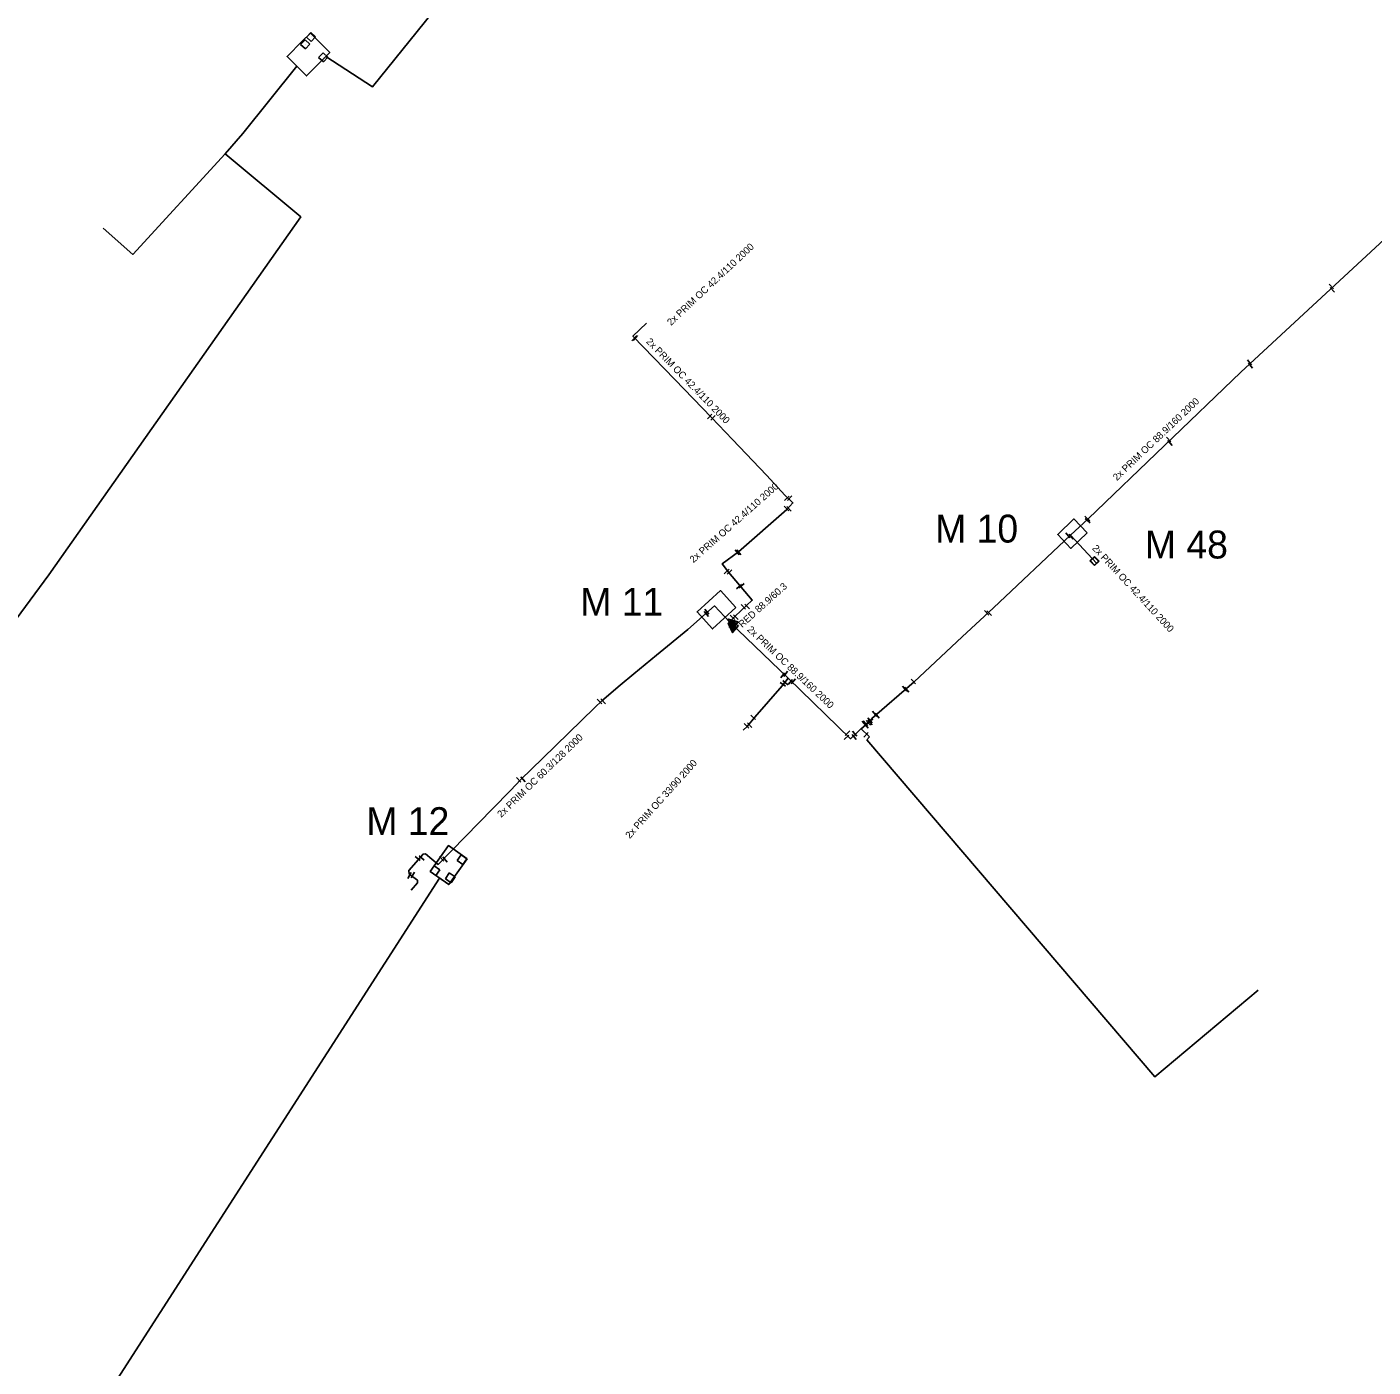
# Model space of a CAD drawing. Extents: x -642943 to -623314, y -1138561 to -1113539.
# Drawn here: x -642361.3 to -642216.7, y -1115211.3 to -1115067.2 of the extents above; entities that cross this region are included whole.
import ezdxf

# ---------------------------------------------------------------- set-up
doc = ezdxf.new("R2010")
doc.units = 0
for name, color, linetype in [('horkovod armatury', 7, 'Continuous'), ('horkovod dimenze', 7, 'Continuous'), ('horkovod předisol', 7, 'Continuous'), ('horkovod sváry', 7, 'Continuous'), ('horkovod trasa', 7, 'Continuous'), ('horkovod zrušený', 7, 'Continuous'), ('horkovod číslo šachty', 7, 'Continuous'), ('horkovod šachty', 7, 'Continuous')]:
    doc.layers.add(name, color=color, linetype=linetype)

# ---------------------------------------------------------------- blocks, each defined once
blk = doc.blocks.new('SPH')
at = {"layer": 'horkovod sváry'}
blk.add_line((0, -0.035), (0, 0.035), dxfattribs=at)
blk = doc.blocks.new('POINT_DISPLAY')
blk.add_line((0, 0), (0, 0))
blk = doc.blocks.new('SREDU')
at = {"layer": 'horkovod armatury'}
for points in [[(-0.05, -0.05), (0.051, 0), (-0.05, 0.05), (-0.05, -0.05)], [(-0.034, -0.025), (0.018, 0), (-0.034, 0.025), (-0.034, -0.025)], [(-0.025, -0.012), (0.001, 0), (-0.025, 0.012), (-0.025, -0.012)]]:
    blk.add_lwpolyline(points, dxfattribs=at)

msp = doc.modelspace()

# ---------------------------------------------------------------- linework, layer by layer
at = {"layer": 'horkovod předisol'}
for p, q in [((-642249.21, -1115121.86), (-642246.37, -1115124.91)), ((-642279.54, -1115137.23), (-642285.84, -1115131.16))]:
    msp.add_line(p, q, dxfattribs=at)
for points in [[(-642194.19, -1115070.71), (-642203.14, -1115078.74), (-642210.42, -1115085.39), (-642214.98, -1115089.6), (-642230.9, -1115104.35), (-642247.3, -1115120.1), (-642249.21, -1115121.86)], [(-642284.87, -1115123.65), (-642279.69, -1115119.09), (-642279.03, -1115118.38), (-642279.85, -1115117.58), (-642281.88, -1115115.42), (-642285.53, -1115111.57), (-642287.77, -1115109.22), (-642291.74, -1115105.12), (-642296.23, -1115100.48), (-642294.77, -1115099.06)], [(-642249.21, -1115121.86), (-642257.49, -1115129.67), (-642260.83, -1115132.77), (-642266.02, -1115137.62), (-642270.55, -1115141.56)], [(-642285.84, -1115131.16), (-642285.23, -1115130.56), (-642283.4, -1115128.84), (-642285.95, -1115125.84), (-642286.65, -1115124.94), (-642284.87, -1115123.65)], [(-642285.84, -1115131.16), (-642287.45, -1115129.45), (-642290.33, -1115131.99), (-642293.71, -1115134.74), (-642296.12, -1115136.74), (-642297.6, -1115137.99), (-642299.56, -1115139.67), (-642300.31, -1115140.39), (-642305.95, -1115145.86), (-642308.26, -1115148.1), (-642309.4, -1115149.28), (-642311.31, -1115151.27), (-642317.17, -1115157.24), (-642318.51, -1115156.1), (-642318.77, -1115156.13), (-642320.31, -1115157.9), (-642320.26, -1115158.27), (-642319.39, -1115158.94), (-642319.37, -1115159.2), (-642320.04, -1115160.01)], [(-642279.54, -1115137.23), (-642280.19, -1115138.04), (-642283.11, -1115141.41), (-642283.95, -1115142.4), (-642284.39, -1115142.8)], [(-642270.55, -1115141.56), (-642272.86, -1115143.73), (-642279.54, -1115137.23)], [(-642270.55, -1115141.56), (-642270.48, -1115141.63), (-642271.69, -1115142.68), (-642270.87, -1115143.46)]]:
    msp.add_lwpolyline(points, dxfattribs=at)
at = {"layer": 'horkovod trasa'}
for p, q in [((-642249.21, -1115121.86), (-642246.37, -1115124.91)), ((-642279.54, -1115137.23), (-642285.84, -1115131.16)), ((-642271.08, -1115143.84), (-642270.79, -1115143.54)), ((-642270.87, -1115143.46), (-642270.79, -1115143.54))]:
    msp.add_line(p, q, dxfattribs=at)
for points in [[(-642329.22, -1115070.42), (-642324.22, -1115073.68), (-642296.32, -1115039.07), (-642267.43, -1115007.95), (-642277.18, -1114996), (-642304.7, -1114983.75), (-642293.54, -1114943.83), (-642293.69, -1114923.7)], [(-642332.35, -1115071.45), (-642338.16, -1115078.7), (-642340.05, -1115080.88), (-642331.92, -1115087.66), (-642359.01, -1115126.11), (-642369.97, -1115140.94), (-642374.96, -1115138.17)], [(-642194.19, -1115070.71), (-642203.14, -1115078.74), (-642210.42, -1115085.39), (-642214.98, -1115089.6), (-642230.9, -1115104.35), (-642247.3, -1115120.1), (-642249.21, -1115121.86)], [(-642340.05, -1115080.88), (-642349.96, -1115091.69), (-642353.15, -1115088.86)], [(-642284.87, -1115123.65), (-642279.69, -1115119.09), (-642279.03, -1115118.38), (-642279.85, -1115117.58), (-642281.88, -1115115.42), (-642285.53, -1115111.57), (-642287.77, -1115109.22), (-642291.74, -1115105.12), (-642296.23, -1115100.48), (-642294.77, -1115099.06)], [(-642249.21, -1115121.86), (-642257.49, -1115129.67), (-642260.83, -1115132.77), (-642266.02, -1115137.62), (-642270.55, -1115141.56)], [(-642285.84, -1115131.16), (-642285.23, -1115130.56), (-642283.4, -1115128.84), (-642285.95, -1115125.84), (-642286.65, -1115124.94), (-642284.87, -1115123.65)], [(-642285.84, -1115131.16), (-642287.45, -1115129.45), (-642290.33, -1115131.99), (-642293.71, -1115134.74), (-642296.12, -1115136.74), (-642297.6, -1115137.99), (-642299.56, -1115139.67), (-642300.31, -1115140.39), (-642305.95, -1115145.86), (-642308.26, -1115148.1), (-642309.4, -1115149.28), (-642311.31, -1115151.27), (-642317.17, -1115157.24), (-642318.51, -1115156.1), (-642318.77, -1115156.13), (-642320.31, -1115157.9), (-642320.26, -1115158.27), (-642319.39, -1115158.94), (-642319.37, -1115159.2), (-642320.04, -1115160.01)], [(-642279.54, -1115137.23), (-642280.19, -1115138.04), (-642283.11, -1115141.41), (-642283.95, -1115142.4), (-642284.39, -1115142.8)], [(-642270.55, -1115141.56), (-642272.86, -1115143.73), (-642279.54, -1115137.23)], [(-642270.55, -1115141.56), (-642270.48, -1115141.63), (-642271.69, -1115142.68), (-642270.87, -1115143.46)], [(-642271.08, -1115143.84), (-642240.15, -1115180.05), (-642229.02, -1115170.76)]]:
    msp.add_lwpolyline(points, dxfattribs=at)
at = {"layer": 'horkovod zrušený'}
msp.add_line((-642358.66, -1115223.47), (-642317.01, -1115158.7), dxfattribs=at)
for points in [[(-642247.42, -1115121.62), (-642248.84, -1115120.11), (-642250.57, -1115121.78), (-642249.16, -1115123.27), (-642247.42, -1115121.62)], [(-642285.18, -1115129.62), (-642286.83, -1115127.81), (-642289.34, -1115130.11), (-642287.68, -1115131.92), (-642285.18, -1115129.62)], [(-642314.05, -1115156.62), (-642316.06, -1115155.21), (-642318.01, -1115157.99), (-642316.01, -1115159.4), (-642314.05, -1115156.62)]]:
    msp.add_lwpolyline(points, dxfattribs=at)
at = {"layer": 'horkovod šachty'}
for p, q in [((-642331.46, -1115068.61), (-642331.94, -1115069.11)), ((-642330.95, -1115069.09), (-642331.46, -1115068.61)), ((-642330.84, -1115067.82), (-642331.32, -1115068.33)), ((-642331.32, -1115068.33), (-642330.81, -1115068.8)), ((-642330.33, -1115068.29), (-642330.84, -1115067.82)), ((-642330.81, -1115068.8), (-642330.33, -1115068.29)), ((-642331.94, -1115069.11), (-642331.43, -1115069.59)), ((-642331.43, -1115069.59), (-642330.95, -1115069.09)), ((-642329.53, -1115070.02), (-642330, -1115070.53)), ((-642329.01, -1115070.49), (-642329.53, -1115070.02)), ((-642330, -1115070.53), (-642329.48, -1115071)), ((-642329.48, -1115071), (-642329.01, -1115070.49)), ((-642247.12, -1115124.61), (-642246.61, -1115124.14)), ((-642246.64, -1115125.13), (-642247.12, -1115124.61)), ((-642247.05, -1115124.62), (-642246.61, -1115124.21)), ((-642246.64, -1115125.06), (-642247.05, -1115124.62)), ((-642246.64, -1115125.13), (-642246.13, -1115124.65)), ((-642246.64, -1115125.06), (-642246.2, -1115124.65)), ((-642246.61, -1115124.14), (-642246.13, -1115124.65)), ((-642246.61, -1115124.21), (-642246.2, -1115124.65)), ((-642314.7, -1115156.21), (-642315.13, -1115156.82)), ((-642315.13, -1115156.82), (-642314.52, -1115157.25)), ((-642314.09, -1115156.64), (-642314.7, -1115156.21)), ((-642314.52, -1115157.25), (-642314.09, -1115156.64)), ((-642317.58, -1115157.38), (-642318.01, -1115157.99)), ((-642318.01, -1115157.99), (-642317.4, -1115158.42)), ((-642316.96, -1115157.81), (-642317.58, -1115157.38)), ((-642317.4, -1115158.42), (-642316.96, -1115157.81)), ((-642315.96, -1115158.16), (-642316.38, -1115158.78)), ((-642315.34, -1115158.57), (-642315.96, -1115158.16)), ((-642315.75, -1115159.2), (-642315.34, -1115158.57)), ((-642316.38, -1115158.78), (-642315.75, -1115159.2))]:
    msp.add_line(p, q, dxfattribs=at)
msp.add_lwpolyline([(-642331.77, -1115068.78), (-642333.39, -1115070.41), (-642331.31, -1115072.49), (-642328.8, -1115069.98), (-642330.88, -1115067.9), (-642331.77, -1115068.78)], dxfattribs=at)

# ---------------------------------------------------------------- block references
at = {"layer": 'horkovod armatury'}
for p, xscale, yscale, rotation in [((-642285.61, -1115131.21), 10.000004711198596, 10.000004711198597, 138.02346569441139), ((-642285.58, -1115131.62), 9.9999987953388, 9.999998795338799, 140.7128512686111)]:
    msp.add_blockref('SREDU', p, dxfattribs=dict(at, xscale=xscale, yscale=yscale, rotation=rotation))
at = {"layer": 'horkovod sváry'}
for p, xscale, yscale, rotation in [((-642221.17, -1115095.14), 9.999996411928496, 9.999996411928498, 43.44789718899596), ((-642221.07, -1115095.49), 9.999984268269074, 9.999984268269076, 42.9943262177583), ((-642296.1, -1115100.71), 10.000000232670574, 10.000000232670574, -42.781943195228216), ((-642295.96, -1115100.67), 10.000000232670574, 10.000000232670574, -42.781943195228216), ((-642229.98, -1115103.3), 9.999977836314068, 9.999977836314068, 38.39150709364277), ((-642229.86, -1115103.63), 9.999989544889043, 9.999989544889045, 41.04235929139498), ((-642287.97, -1115109.11), 10.000000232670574, 10.000000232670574, -42.781943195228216), ((-642287.62, -1115109.25), 9.99999797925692, 9.99999797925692, -43.108534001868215), ((-642238.66, -1115111.57), 9.999989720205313, 9.999989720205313, 41.5915519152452), ((-642238.52, -1115111.94), 9.999986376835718, 9.999986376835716, 40.61220467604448), ((-642279.69, -1115117.9), 9.99998715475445, 9.99998715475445, -46.18675416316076), ((-642279.39, -1115117.88), 9.999986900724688, 9.99998690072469, -43.898348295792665), ((-642279.72, -1115118.99), 10.000012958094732, 10.000012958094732, 43.5228236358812), ((-642279.45, -1115119.01), 10.00000408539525, 10.00000408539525, 44.620603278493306), ((-642247.39, -1115120.06), 10.000013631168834, 10.000013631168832, 47.429337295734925), ((-642247.37, -1115120.3), 10.000003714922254, 10.000003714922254, 49.01039855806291), ((-642249.5, -1115121.87), 10.0000269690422, 10.0000269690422, 37.93893657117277), ((-642249.12, -1115122.01), 10.000018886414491, 10.000018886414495, 37.65197844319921), ((-642285.03, -1115123.69), 10.000014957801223, 10.000014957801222, 38.072739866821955), ((-642284.84, -1115123.71), 10.000008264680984, 10.000008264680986, 40.0301448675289), ((-642286.15, -1115125.76), 9.999996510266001, 9.999996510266, -47.531690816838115), ((-642285.85, -1115125.81), 9.9999887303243, 9.9999887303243, -46.34111516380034), ((-642284.82, -1115127.39), 9.999992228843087, 9.999992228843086, -48.39597371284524), ((-642284.54, -1115127.28), 10.000002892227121, 10.000002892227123, -49.50340681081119), ((-642284.37, -1115129.55), 10.000026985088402, 10.000026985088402, 41.76032102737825), ((-642283.94, -1115129.53), 9.99999804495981, 9.999998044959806, 44.50193274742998), ((-642288.33, -1115130.33), 10.000016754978, 10.000016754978, 41.88389081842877), ((-642288.28, -1115130.07), 10.00002500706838, 10.00002500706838, 40.64892818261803), ((-642285.53, -1115130.68), 10.000007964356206, 10.000007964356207, 48.97824667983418), ((-642285.16, -1115130.66), 9.999995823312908, 9.999995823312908, 46.67912126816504), ((-642258.21, -1115130.21), 10.000004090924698, 10.000004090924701, 44.00647008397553), ((-642257.93, -1115130.23), 9.999980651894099, 9.999980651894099, 46.14788295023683), ((-642285.64, -1115131.51), 9.999993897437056, 9.999993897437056, -40.45419727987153), ((-642285.35, -1115131.52), 10.000017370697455, 10.000017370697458, -39.84567585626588), ((-642280.13, -1115136.92), 10.000000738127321, 10.00000073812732, -36.25378036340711), ((-642279.81, -1115136.76), 9.99999068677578, 9.999990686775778, -36.87000436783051), ((-642280.13, -1115137.88), 9.999986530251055, 9.999986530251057, 54.226417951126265), ((-642279.85, -1115137.71), 9.99998986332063, 9.99998986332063, 49.690788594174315), ((-642279.31, -1115137.63), 10.000009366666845, 10.000009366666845, -42.14931473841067), ((-642278.98, -1115137.56), 9.999984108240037, 9.999984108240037, -42.30437881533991), ((-642267.02, -1115138.35), 9.999996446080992, 9.99999644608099, 43.024909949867), ((-642266.8, -1115138.46), 9.999978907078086, 9.999978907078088, 43.175917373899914), ((-642266.09, -1115137.58), 10.00000528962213, 10.00000528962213, 44.31515034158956), ((-642299.82, -1115139.73), 10.000008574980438, 10.00000857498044, 43.12967723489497), ((-642299.42, -1115139.71), 9.999985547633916, 9.999985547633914, 43.66775382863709), ((-642283.31, -1115141.43), 10.000020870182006, 10.000020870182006, 46.577954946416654), ((-642270.25, -1115141.06), 9.999989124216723, 9.999989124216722, 38.290086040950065), ((-642269.98, -1115141.25), 9.999997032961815, 9.999997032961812, 37.75695230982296), ((-642284.03, -1115142.34), 9.999997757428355, 9.999997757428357, 46.5936233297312), ((-642283.68, -1115142.28), 10.000000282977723, 10.000000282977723, 45.18262262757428), ((-642271.36, -1115142.11), 10.000020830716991, 10.000020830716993, 39.06265595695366), ((-642271.25, -1115142.08), 10.000005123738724, 10.000005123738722, 39.66076319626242), ((-642271.16, -1115142.32), 10.000021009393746, 10.000021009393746, 38.93631690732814), ((-642270.94, -1115142.02), 10.000008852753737, 10.000008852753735, 41.440729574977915), ((-642270.76, -1115141.76), 10.000006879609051, 10.000006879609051, 41.34791341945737), ((-642270.74, -1115141.97), 9.999979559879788, 9.999979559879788, 42.13759477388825), ((-642273.28, -1115143.58), 10.000007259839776, 10.000007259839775, -48.441705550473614), ((-642273.16, -1115143.13), 10.00003058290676, 10.000030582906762, -46.034095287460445), ((-642272.46, -1115143.54), 10.000001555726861, 10.000001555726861, 38.380507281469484), ((-642272.39, -1115143.17), 10.000015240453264, 10.000015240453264, 40.256976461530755), ((-642271.17, -1115143.31), 10.00000810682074, 10.00000810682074, -42.75173651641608), ((-642308.5, -1115148.15), 9.999999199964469, 9.999999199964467, 42.169523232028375), ((-642308.05, -1115148.09), 9.999985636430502, 9.999985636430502, 42.967331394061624), ((-642319.35, -1115156.6), 9.999979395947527, 9.999979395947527, 49.47276051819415), ((-642318.93, -1115156.54), 10.000006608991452, 10.000006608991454, 47.31906729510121), ((-642316.77, -1115156.63), 9.999980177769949, 9.999980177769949, 43.349941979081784), ((-642316.42, -1115156.71), 9.999993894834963, 9.99999389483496, 39.45456601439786), ((-642320.23, -1115158.43), 10.000022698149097, 10.000022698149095, -29.054578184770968), ((-642319.88, -1115158.38), 10.000003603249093, 10.000003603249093, -32.03708647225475)]:
    msp.add_blockref('SPH', p, dxfattribs=dict(at, xscale=xscale, yscale=yscale, rotation=rotation))
at = {"layer": 'horkovod šachty'}
for p in [(-642330.82, -1115068.31), (-642331.44, -1115069.1), (-642329.5, -1115070.51), (-642246.62, -1115124.64), (-642314.6, -1115156.73), (-642317.48, -1115157.9), (-642315.85, -1115158.67)]:
    msp.add_blockref('POINT_DISPLAY', p, dxfattribs=at)

# ---------------------------------------------------------------- texts
at = {"layer": 'horkovod dimenze'}
for s, rotation, p in [('2x PRIM OC 42.4/110 2000', 43.1913, (-642292.13, -1115099.38)), ('2x PRIM OC 42.4/110 2000', 314.1873, (-642294.86, -1115101.11)), ('2x PRIM OC 88.9/160 2000', 43.6144, (-642244.22, -1115116.05)), ('2x PRIM OC 42.4/110 2000', 41.5128, (-642289.73, -1115124.88)), ('2x PRIM OC 42.4/110 2000', 312.786, (-642246.93, -1115123.31)), ('RED 88.9/60.3', 41.8077, (-642284.49, -1115131.84)), ('2x PRIM OC 88.9/160 2000', 316.5941, (-642284.01, -1115132.08)), ('2x PRIM OC 60.3/128 2000', 44.1289, (-642310.38, -1115152.25)), ('2x PRIM OC 33/90 2000', 48.1468, (-642296.56, -1115154.52))]:
    msp.add_text(s, height=0.75, rotation=rotation, dxfattribs=at).set_placement(p)
at = {"layer": 'horkovod číslo šachty'}
for s, p in [('M 10', (-642263.75, -1115122.65)), ('M 48', (-642241.21, -1115124.36)), ('M 11', (-642301.88, -1115130.52)), ('M 12', (-642324.87, -1115154.09))]:
    msp.add_text(s, height=3, dxfattribs=at).set_placement(p)

doc.saveas('drawing.dxf')
